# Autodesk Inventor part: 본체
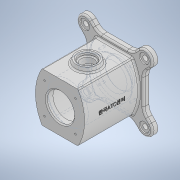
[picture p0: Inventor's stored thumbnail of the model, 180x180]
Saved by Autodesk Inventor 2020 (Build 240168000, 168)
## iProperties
Created: 2022-01
Part Number: 본체
Material: 일반
Document SubType Name: Modeling
Designer: user
Density: 1 g/cm^3
Appearance: 기본값
Mass: 458.422 g
Surface Area: 905.599 cm^2
Volume: 458.422 cm^3
Author: user
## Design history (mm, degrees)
sketch "스케치1"
  geometry: L1 (-32.942, -45)-(32.942, -45); L2 (32.942, 45)-(-32.942, 45); L3 (-45, -45)-(45, 45); L4 (45, -45)-(-45, 45); L5 (0, 0)-(0, -45); A1 r 90 centre (45, 0) between (-32.942, 45) and (-32.942, -45); A2 r 90 centre (-45, 0) between (32.942, -45) and (32.942, 45)
  constraints: 10 end point, 4 point on circle, 3 symmetric about line, 2 centre point, 2 midpoint, 1 horizontal, 1 parallel, 1 other
  dimensions: "d2" = 180 diameter of A1; "d3" = 90 distance between parallel lines of L1 L2; "d4" = 90 distance of A1.centre A2.centre
extrude "돌출1" new body sketch "스케치1" distance "d5" = 110; taper "d6" = 0 deg
sketch "스케치2"
  geometry: L1 (53, -53)-(-53, -53); L2 (-53, -53)-(-53, 53); L3 (-53, 53)-(53, 53); L4 (53, 53)-(53, -53); L5 (53, -53)-(-53, 53); L6 (-53, -53)-(53, 53); L7 (0, 0)-(0, 74); L8 (54.447, -54.447)-(-54.447, 54.447); L9 (65.054, -43.841)-(-43.841, 65.054); L10 (-65.054, 43.841)-(43.841, -65.054); L11 (-54.447, -54.447)-(54.447, 54.447); L12 (-43.841, -65.054)-(65.054, 43.841); L13 (43.841, 65.054)-(-65.054, -43.841); A1 r 15 centre (54.447, -54.447) between (43.841, -65.054) and (65.054, -43.841); A2 r 15 centre (-54.447, 54.447) between (-43.841, 65.054) and (-65.054, 43.841); A3 r 15 centre (-54.447, -54.447) between (-65.054, -43.841) and (-43.841, -65.054); A4 r 15 centre (54.447, 54.447) between (65.054, 43.841) and (43.841, 65.054); 9 further points
  constraints: 30 end point, 8 point on circle, 8 tangent, 5 midpoint, 4 centre point, 4 parallel, 2 perpendicular, 2 point on line, 1 horizontal, 1 vertical
  dimensions: "d7" = 106 distance of L2.end L3.end; "d8" = 106 distance of L1.end L2.end; "d10" = 154 distance of L11.start L11.end; "d11" = 154 distance of L8.start L8.end; "d12" = 30 distance between parallel lines of L12 L13; "d13" = 30 distance between parallel lines of L10 L9
extrude "돌출2" join sketch "스케치2" distance "d14" = 10; taper "d15" = 0 deg
fillet "모깎기1" dims "d16" = 20
sketch "스케치3"
  geometry: L1 (25, 110)-(25, 98); L2 (25, 98)-(-25, 98); L3 (-25, 98)-(-25, 110); L4 (32.942, 110)-(-32.942, 110) reference; L5 (-25, 122)-(25, 98); L6 (25, 122)-(-25, 98); L7 (-25, 12)-(25, 12); L8 (25, 12)-(25, 0); L9 (-25, 0)-(-25, 12); L10 (-25, 12)-(25, -12); L11 (25, 12)-(-25, -12); L12 (-23.503, 0)-(23.503, 0) reference; L13 (23.503, 0)-(37.645, 0) reference; L14 (-37.645, 0)-(-23.503, 0) reference; L15 (25, 110)-(-25, 110); L16 (0, 55)-(-37, 55); L17 (-45, 10)-(-45, 110) reference; L18 (-37, 55)-(-37, 98); L19 (-37, 98)-(-25, 98); L20 (-37, 12)-(-25, 12); L21 (-37, 55)-(-37, 12); L22 (0, 110)-(0, 0); 2 further points
  constraints: 34 end point, 5 midpoint, 4 point on line, 3 perpendicular, 2 parallel, 2 symmetric about line, 2 vertical, 1 horizontal
  dimensions: "d17" = 50 distance of L1.end L2.end; "d21" = 37 distance of L16.start L16.end; "d22" = 86 distance between parallel lines of L20 L19; "d23" = 12 distance between parallel lines of L4 L2; "d24" = 12 distance between parallel lines of L12 L7
revolve "회전1" sketch "스케치3" stored, may be unused: angle "d25" = 90 deg
node "작업 평면1"
sketch "스케치4"
  geometry: L1 (0, 0)-(0, 60); C1 r 20 at (0, 60)
  constraints: 2 end point, 1 centre point, 1 coincident, 1 vertical
  dimensions: "d27" = 60 distance of L1.start L1.end; "d28" = 40 diameter of C1
extrude "돌출3" join sketch "스케치4" stored distance "d29" = 5; taper "d30" = 15 deg
sketch "스케치5"
  geometry: C1 r 15 at (0, 0); 1 further point
  constraints: 1 centre point
  dimensions: "d31" = 30 diameter of C1
extrude "돌출4" cut sketch "스케치5" distance "d32" = 5; taper "d33" = 0 deg
sketch "스케치6"
  geometry: C1 r 12 at (0, 0); 1 further point
  constraints: 1 centre point
  dimensions: "d34" = 24 diameter of C1
extrude "돌출5" cut sketch "스케치6" distance "d35" = 48; taper "d36" = 0 deg
sketch "스케치7"
  geometry: C1 r 9 at (54.447, 54.447); A1 r 15 centre (54.447, 54.447) between (65.054, 43.841) and (43.841, 65.054) reference; 1 further point
  constraints: 1 centre point, 1 coincident
  dimensions: "d37" = 18 diameter of C1
extrude "돌출6" cut sketch "스케치7" distance "d38" = 2; taper "d39" = 0 deg
sketch "스케치8"
  geometry: C1 r 4.5 at (0, 0); 1 further point
  constraints: 1 centre point
  dimensions: "d40" = 9 diameter of C1
extrude "돌출7" cut sketch "스케치8" stored distance "d41" = 2; taper "d42" = 0 deg
fillet "모깎기2" dims "d46" = 3
fillet "모깎기3" dims "d47" = 3
fillet "모깎기4" dims "d48" = 3
fillet "모깎기5" dims "d49" = 3
fillet "모깎기6" dims "d50" = 3
chamfer "모따기1" distance "d51" = 2; stored, may be unused: second distance "d52" = 2, angle "d53" = 45 deg
sketch "스케치9"
  geometry: L1 (-28.284, 28.284)-(28.284, -28.284); L2 (-48.784, 7.784)-(7.784, -48.784); L3 (48.784, -7.784)-(-7.784, 48.784); L4 (0, 0)-(80, 0); L5 (-28.284, -28.284)-(28.284, 28.284); L6 (-41.284, -15.284)-(15.284, 41.284); L7 (41.284, 15.284)-(-15.284, -41.284); L8 (0, 0)-(80, 0); C1 r 25 at (0, 0) reference; A1 r 28.991 centre (-28.284, 28.284) between (-7.784, 48.784) and (-48.784, 7.784); A2 r 28.991 centre (28.284, -28.284) between (7.784, -48.784) and (48.784, -7.784); A3 r 18.385 centre (-28.284, -28.284) between (-41.284, -15.284) and (-15.284, -41.284); A4 r 18.385 centre (28.284, 28.284) between (41.284, 15.284) and (15.284, 41.284)
  constraints: 20 end point, 8 point on circle, 8 tangent, 4 centre point, 2 equal length, 2 horizontal, 2 midpoint, 2 parallel
  dimensions: "d77" = 45 deg angle of L1 L4; "d78" = 45 deg angle of L8 L5; "d79" = 80 distance of L5.start L5.end; "d80" = 80 distance of L1.start L1.end
hole "구멍1" sketch "스케치9" at (28.284, -28.284), (28.284, 28.284), (-28.284, 28.284), (-28.284, -28.284) diameter "d57" = 3.242; stored, may be unused: countersink angle "d61" = 90 deg, drill point angle "d63" = 118 deg; dims "d58" = 8, "d59" = 4, "d60" = 2, "d62" = 10
node "작업 평면2"
node "작업 평면3"
sketch "스케치10" dims "d2" = 180, "d3" = 90, "d4" = 90
  geometry: L1 (53, 40)-(53, 80) reference; L2 (43.841, 0)-(69.447, 0) reference; 3 further points
  constraints: 1 other
  dimensions: "d69" = 53 distance from line of L1 point (0, 60); "d70" = 60 distance from line of L2 point (0, 60)
feature "엠보싱1" sketch "스케치10" dims "d2" = 180, "d3" = 90, "d4" = 90, "d71" = 0.5, "d72" = 0
node "솔리드1"
pattern_circular "원형 패턴1" dims angle "d44" = 360 deg
mirror "미러3"
feature "A9D066F2-1C7D-4E18-AEED-F7BC21143FA4" dims "d57" = 3.242, "d58" = 8, "d59" = 4, "d60" = 2, "d61" = 90 deg, "d62" = 10, "d63" = 118 deg
other parameters: "d26" = 53, "d67" = -55, "d68" = 45
